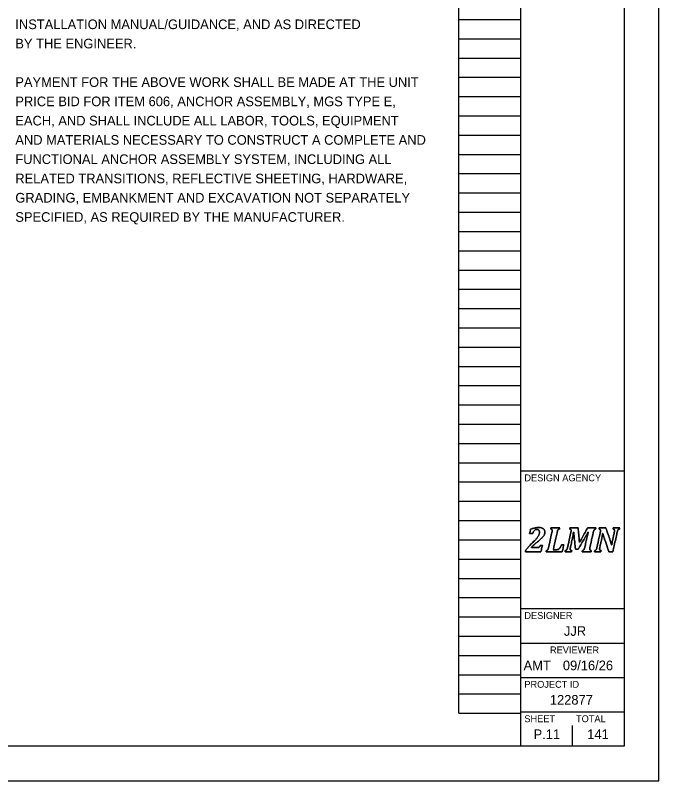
# Model space of a CAD drawing. Extents: x -17.1 to 50.1, y -5.2 to 23.
# Drawn here: x 24.66 to 34, y 0 to 11.12 of the extents above; entities that cross this region are included whole.
import ezdxf

# ---------------------------------------------------------------- set-up
doc = ezdxf.new("R2010")
doc.units = 0
for name, color, linetype in [('SH_Border', 7, 'Continuous'), ('SH_Cut_Line', 7, 'Continuous'), ('SH_Data', 7, 'Continuous'), ('SH_Text', 7, 'Continuous')]:
    doc.layers.add(name, color=color, linetype=linetype)

msp = doc.modelspace()

# ---------------------------------------------------------------- linework, layer by layer
at = {"layer": 'SH_Border'}
for p, q in [((32, 0.5), (32, 21.5)), ((32, 4.5), (33.5, 4.5)), ((32, 2.5), (33.5, 2.5)), ((32, 2), (33.5, 2)), ((32, 1.5), (33.5, 1.5)), ((32, 1), (33.5, 1))]:
    msp.add_line(p, q, dxfattribs=at)
msp.add_lwpolyline([(1.5, 21.5), (33.5, 21.5), (33.5, 0.5), (1.5, 0.5)], close=True, dxfattribs=at)
at = {"layer": 'SH_Cut_Line'}
msp.add_lwpolyline([(0, 0), (34, 0), (34, 22), (0, 22)], close=True, dxfattribs=at)
at = {"layer": 'SH_Data'}
for p, q in [((31.1, 0.98), (31.1, 21.14)), ((32, 0.98), (32, 21.14)), ((31.1, 11.06), (32, 11.06)), ((31.1, 10.78), (32, 10.78)), ((31.1, 10.5), (32, 10.5)), ((31.1, 10.22), (32, 10.22)), ((31.1, 9.94), (32, 9.94)), ((31.1, 9.66), (32, 9.66)), ((31.1, 9.38), (32, 9.38)), ((31.1, 9.1), (32, 9.1)), ((31.1, 8.82), (32, 8.82)), ((31.1, 8.54), (32, 8.54)), ((31.1, 8.26), (32, 8.26)), ((31.1, 7.98), (32, 7.98)), ((31.1, 7.7), (32, 7.7)), ((31.1, 7.42), (32, 7.42)), ((31.1, 7.14), (32, 7.14)), ((31.1, 6.86), (32, 6.86)), ((31.1, 6.58), (32, 6.58)), ((31.1, 6.3), (32, 6.3)), ((31.1, 6.02), (32, 6.02)), ((31.1, 5.74), (32, 5.74)), ((31.1, 5.46), (32, 5.46)), ((31.1, 5.18), (32, 5.18)), ((31.1, 4.9), (32, 4.9)), ((31.1, 4.62), (32, 4.62)), ((31.1, 4.34), (32, 4.34)), ((31.1, 4.06), (32, 4.06)), ((31.1, 3.78), (32, 3.78)), ((31.1, 3.5), (32, 3.5)), ((32.75, 3.5), (32.75, 3.5)), ((31.1, 3.22), (32, 3.22)), ((31.1, 2.94), (32, 2.94)), ((31.1, 2.66), (32, 2.66)), ((31.1, 2.38), (32, 2.38)), ((31.1, 2.1), (32, 2.1)), ((31.1, 1.82), (32, 1.82)), ((31.1, 1.54), (32, 1.54)), ((31.1, 1.26), (32, 1.26)), ((31.1, 0.98), (32, 0.98)), ((32.75, 0.5), (32.75, 0.8)), ((32.375, 0.675), (32.375, 0.675))]:
    msp.add_line(p, q, dxfattribs=at)
for points in [[(32.237, 3.388), (32.246, 3.388), (32.253, 3.389), (32.258, 3.39), (32.263, 3.392), (32.267, 3.394), (32.27, 3.397), (32.273, 3.401), (32.277, 3.408), (32.281, 3.417), (32.281, 3.417), (32.312, 3.417), (32.312, 3.417), (32.312, 3.417), (32.29, 3.326), (32.29, 3.326), (32.29, 3.326), (32.066, 3.326), (32.066, 3.326), (32.066, 3.326), (32.069, 3.343), (32.069, 3.343), (32.078, 3.358), (32.091, 3.375), (32.106, 3.394), (32.122, 3.412), (32.144, 3.435), (32.172, 3.462), (32.197, 3.486), (32.217, 3.506), (32.23, 3.521), (32.243, 3.537), (32.253, 3.551), (32.259, 3.566), (32.266, 3.58), (32.269, 3.595), (32.269, 3.61), (32.269, 3.622), (32.266, 3.632), (32.26, 3.64), (32.253, 3.647), (32.245, 3.65), (32.234, 3.65), (32.22, 3.65), (32.208, 3.646), (32.198, 3.636), (32.188, 3.627), (32.18, 3.613), (32.172, 3.593), (32.172, 3.593), (32.126, 3.593), (32.126, 3.593), (32.126, 3.593), (32.14, 3.654), (32.14, 3.654), (32.166, 3.663), (32.188, 3.669), (32.205, 3.673), (32.223, 3.676), (32.24, 3.678), (32.258, 3.678), (32.278, 3.678), (32.295, 3.675), (32.309, 3.669), (32.322, 3.664), (32.332, 3.656), (32.339, 3.646), (32.345, 3.637), (32.348, 3.626), (32.348, 3.613), (32.348, 3.602), (32.346, 3.591), (32.342, 3.581), (32.339, 3.571), (32.333, 3.56), (32.324, 3.549), (32.315, 3.539), (32.304, 3.526), (32.289, 3.513), (32.275, 3.499), (32.254, 3.482), (32.228, 3.46), (32.216, 3.45), (32.202, 3.438), (32.188, 3.425), (32.174, 3.412), (32.162, 3.4), (32.154, 3.391), (32.154, 3.391), (32.153, 3.388), (32.153, 3.388), (32.153, 3.388), (32.237, 3.388), (32.237, 3.388)], [(32.237, 3.388), (32.237, 3.388), (32.153, 3.388), (32.153, 3.388), (32.153, 3.388), (32.154, 3.391), (32.154, 3.391), (32.162, 3.4), (32.174, 3.412), (32.188, 3.425), (32.202, 3.438), (32.216, 3.45), (32.228, 3.46), (32.254, 3.482), (32.275, 3.499), (32.289, 3.513), (32.304, 3.526), (32.315, 3.539), (32.324, 3.549), (32.333, 3.56), (32.339, 3.571), (32.342, 3.581), (32.346, 3.591), (32.348, 3.602), (32.348, 3.613), (32.348, 3.626), (32.345, 3.637), (32.339, 3.646), (32.332, 3.656), (32.322, 3.664), (32.309, 3.669), (32.295, 3.675), (32.278, 3.678), (32.258, 3.678), (32.24, 3.678), (32.223, 3.676), (32.205, 3.673), (32.188, 3.669), (32.166, 3.663), (32.14, 3.654), (32.14, 3.654), (32.126, 3.593), (32.126, 3.593), (32.126, 3.593), (32.172, 3.593), (32.172, 3.593), (32.18, 3.613), (32.188, 3.627), (32.198, 3.636), (32.208, 3.646), (32.22, 3.65), (32.234, 3.65), (32.245, 3.65), (32.253, 3.647), (32.26, 3.64), (32.266, 3.632), (32.269, 3.622), (32.269, 3.61), (32.269, 3.595), (32.266, 3.58), (32.259, 3.566), (32.253, 3.551), (32.243, 3.537), (32.23, 3.521), (32.217, 3.506), (32.197, 3.486), (32.172, 3.462), (32.144, 3.435), (32.122, 3.412), (32.106, 3.394), (32.091, 3.375), (32.078, 3.358), (32.069, 3.343), (32.069, 3.343), (32.066, 3.326), (32.066, 3.326), (32.066, 3.326), (32.29, 3.326), (32.29, 3.326), (32.29, 3.326), (32.312, 3.417), (32.312, 3.417), (32.312, 3.417), (32.281, 3.417), (32.281, 3.417), (32.277, 3.408), (32.273, 3.401), (32.27, 3.397), (32.267, 3.394), (32.263, 3.392), (32.258, 3.39), (32.253, 3.389), (32.246, 3.388), (32.237, 3.388)], [(32.518, 3.356), (32.527, 3.356), (32.533, 3.357), (32.538, 3.358), (32.542, 3.36), (32.546, 3.362), (32.55, 3.365), (32.554, 3.368), (32.558, 3.372), (32.562, 3.377), (32.567, 3.382), (32.571, 3.388), (32.576, 3.397), (32.58, 3.405), (32.585, 3.415), (32.589, 3.427), (32.589, 3.427), (32.624, 3.427), (32.624, 3.427), (32.624, 3.427), (32.598, 3.326), (32.598, 3.326), (32.598, 3.326), (32.365, 3.326), (32.365, 3.326), (32.365, 3.326), (32.369, 3.343), (32.369, 3.343), (32.376, 3.345), (32.381, 3.348), (32.385, 3.351), (32.389, 3.355), (32.392, 3.36), (32.395, 3.366), (32.398, 3.373), (32.4, 3.382), (32.403, 3.395), (32.403, 3.395), (32.449, 3.605), (32.449, 3.605), (32.452, 3.615), (32.453, 3.625), (32.453, 3.635), (32.453, 3.642), (32.451, 3.647), (32.448, 3.651), (32.444, 3.654), (32.439, 3.656), (32.432, 3.657), (32.432, 3.657), (32.435, 3.674), (32.435, 3.674), (32.435, 3.674), (32.563, 3.674), (32.563, 3.674), (32.563, 3.674), (32.559, 3.657), (32.559, 3.657), (32.552, 3.655), (32.547, 3.652), (32.543, 3.649), (32.539, 3.645), (32.536, 3.64), (32.533, 3.634), (32.531, 3.627), (32.528, 3.618), (32.525, 3.605), (32.525, 3.605), (32.47, 3.356), (32.47, 3.356), (32.47, 3.356), (32.518, 3.356), (32.518, 3.356)], [(32.518, 3.356), (32.518, 3.356), (32.47, 3.356), (32.47, 3.356), (32.47, 3.356), (32.525, 3.605), (32.525, 3.605), (32.528, 3.618), (32.531, 3.627), (32.533, 3.634), (32.536, 3.64), (32.539, 3.645), (32.543, 3.649), (32.547, 3.652), (32.552, 3.655), (32.559, 3.657), (32.559, 3.657), (32.563, 3.674), (32.563, 3.674), (32.563, 3.674), (32.435, 3.674), (32.435, 3.674), (32.435, 3.674), (32.432, 3.657), (32.432, 3.657), (32.439, 3.656), (32.444, 3.654), (32.448, 3.651), (32.451, 3.647), (32.453, 3.642), (32.453, 3.635), (32.453, 3.625), (32.452, 3.615), (32.449, 3.605), (32.449, 3.605), (32.403, 3.395), (32.403, 3.395), (32.4, 3.382), (32.398, 3.373), (32.395, 3.366), (32.392, 3.36), (32.389, 3.355), (32.385, 3.351), (32.381, 3.348), (32.376, 3.345), (32.369, 3.343), (32.369, 3.343), (32.365, 3.326), (32.365, 3.326), (32.365, 3.326), (32.598, 3.326), (32.598, 3.326), (32.598, 3.326), (32.624, 3.427), (32.624, 3.427), (32.624, 3.427), (32.589, 3.427), (32.589, 3.427), (32.585, 3.415), (32.58, 3.405), (32.576, 3.397), (32.571, 3.388), (32.567, 3.382), (32.562, 3.377), (32.558, 3.372), (32.554, 3.368), (32.55, 3.365), (32.546, 3.362), (32.542, 3.36), (32.538, 3.358), (32.533, 3.357), (32.527, 3.356), (32.518, 3.356)], [(32.829, 3.674), (32.829, 3.674), (32.849, 3.461), (32.849, 3.461), (32.849, 3.461), (32.969, 3.674), (32.969, 3.674), (32.969, 3.674), (33.087, 3.674), (33.087, 3.674), (33.087, 3.674), (33.084, 3.657), (33.084, 3.657), (33.077, 3.655), (33.071, 3.652), (33.067, 3.649), (33.064, 3.645), (33.06, 3.64), (33.058, 3.634), (33.055, 3.627), (33.052, 3.618), (33.05, 3.605), (33.05, 3.605), (33.003, 3.395), (33.003, 3.395), (33.002, 3.39), (33.002, 3.387), (33.001, 3.384), (33.001, 3.382), (33.001, 3.379), (33, 3.376), (33, 3.373), (33, 3.369), (33, 3.365), (33, 3.358), (33.002, 3.353), (33.005, 3.349), (33.008, 3.346), (33.014, 3.344), (33.021, 3.343), (33.021, 3.343), (33.018, 3.326), (33.018, 3.326), (33.018, 3.326), (32.89, 3.326), (32.89, 3.326), (32.89, 3.326), (32.893, 3.343), (32.893, 3.343), (32.9, 3.345), (32.906, 3.348), (32.91, 3.351), (32.914, 3.355), (32.917, 3.36), (32.919, 3.366), (32.922, 3.373), (32.925, 3.382), (32.928, 3.395), (32.928, 3.395), (32.951, 3.502), (32.951, 3.502), (32.954, 3.513), (32.957, 3.529), (32.962, 3.548), (32.967, 3.568), (32.972, 3.588), (32.978, 3.609), (32.978, 3.609), (32.973, 3.609), (32.973, 3.609), (32.965, 3.594), (32.957, 3.579), (32.948, 3.563), (32.948, 3.563), (32.833, 3.364), (32.833, 3.364), (32.833, 3.364), (32.792, 3.364), (32.792, 3.364), (32.792, 3.364), (32.775, 3.518), (32.775, 3.518), (32.773, 3.537), (32.772, 3.554), (32.77, 3.569), (32.769, 3.583), (32.768, 3.597), (32.768, 3.611), (32.768, 3.611), (32.764, 3.611), (32.764, 3.611), (32.761, 3.596), (32.758, 3.578), (32.755, 3.558), (32.751, 3.538), (32.747, 3.521), (32.744, 3.507), (32.744, 3.507), (32.72, 3.395), (32.72, 3.395), (32.719, 3.39), (32.718, 3.387), (32.718, 3.384), (32.717, 3.382), (32.717, 3.379), (32.717, 3.376), (32.717, 3.373), (32.716, 3.369), (32.716, 3.365), (32.716, 3.358), (32.718, 3.353), (32.721, 3.349), (32.725, 3.346), (32.73, 3.344), (32.738, 3.343), (32.738, 3.343), (32.734, 3.326), (32.734, 3.326), (32.734, 3.326), (32.641, 3.326), (32.641, 3.326), (32.641, 3.326), (32.644, 3.343), (32.644, 3.343), (32.651, 3.345), (32.657, 3.348), (32.661, 3.351), (32.665, 3.355), (32.668, 3.36), (32.67, 3.366), (32.673, 3.373), (32.676, 3.382), (32.679, 3.395), (32.679, 3.395), (32.725, 3.605), (32.725, 3.605), (32.727, 3.615), (32.728, 3.625), (32.728, 3.635), (32.728, 3.642), (32.727, 3.647), (32.723, 3.651), (32.72, 3.654), (32.715, 3.656), (32.707, 3.657), (32.707, 3.657), (32.711, 3.674), (32.711, 3.674), (32.711, 3.674), (32.829, 3.674), (32.829, 3.674)], [(32.829, 3.674), (32.829, 3.674), (32.711, 3.674), (32.711, 3.674), (32.711, 3.674), (32.707, 3.657), (32.707, 3.657), (32.715, 3.656), (32.72, 3.654), (32.723, 3.651), (32.727, 3.647), (32.728, 3.642), (32.728, 3.635), (32.728, 3.625), (32.727, 3.615), (32.725, 3.605), (32.725, 3.605), (32.679, 3.395), (32.679, 3.395), (32.676, 3.382), (32.673, 3.373), (32.67, 3.366), (32.668, 3.36), (32.665, 3.355), (32.661, 3.351), (32.657, 3.348), (32.651, 3.345), (32.644, 3.343), (32.644, 3.343), (32.641, 3.326), (32.641, 3.326), (32.641, 3.326), (32.734, 3.326), (32.734, 3.326), (32.734, 3.326), (32.738, 3.343), (32.738, 3.343), (32.73, 3.344), (32.725, 3.346), (32.721, 3.349), (32.718, 3.353), (32.716, 3.358), (32.716, 3.365), (32.716, 3.369), (32.717, 3.373), (32.717, 3.376), (32.717, 3.379), (32.717, 3.382), (32.718, 3.384), (32.718, 3.387), (32.719, 3.39), (32.72, 3.395), (32.72, 3.395), (32.744, 3.507), (32.744, 3.507), (32.747, 3.521), (32.751, 3.538), (32.755, 3.558), (32.758, 3.578), (32.761, 3.596), (32.764, 3.611), (32.764, 3.611), (32.768, 3.611), (32.768, 3.611), (32.768, 3.597), (32.769, 3.583), (32.77, 3.569), (32.772, 3.554), (32.773, 3.537), (32.775, 3.518), (32.775, 3.518), (32.792, 3.364), (32.792, 3.364), (32.792, 3.364), (32.833, 3.364), (32.833, 3.364), (32.833, 3.364), (32.948, 3.563), (32.948, 3.563), (32.957, 3.579), (32.965, 3.594), (32.973, 3.609), (32.973, 3.609), (32.978, 3.609), (32.978, 3.609), (32.972, 3.588), (32.967, 3.568), (32.962, 3.548), (32.957, 3.529), (32.954, 3.513), (32.951, 3.502), (32.951, 3.502), (32.928, 3.395), (32.928, 3.395), (32.925, 3.382), (32.922, 3.373), (32.919, 3.366), (32.917, 3.36), (32.914, 3.355), (32.91, 3.351), (32.906, 3.348), (32.9, 3.345), (32.893, 3.343), (32.893, 3.343), (32.89, 3.326), (32.89, 3.326), (32.89, 3.326), (33.018, 3.326), (33.018, 3.326), (33.018, 3.326), (33.021, 3.343), (33.021, 3.343), (33.014, 3.344), (33.008, 3.346), (33.005, 3.349), (33.002, 3.353), (33, 3.358), (33, 3.365), (33, 3.369), (33, 3.373), (33, 3.376), (33.001, 3.379), (33.001, 3.382), (33.001, 3.384), (33.002, 3.387), (33.002, 3.39), (33.003, 3.395), (33.003, 3.395), (33.05, 3.605), (33.05, 3.605), (33.052, 3.618), (33.055, 3.627), (33.058, 3.634), (33.06, 3.64), (33.064, 3.645), (33.067, 3.649), (33.071, 3.652), (33.077, 3.655), (33.084, 3.657), (33.084, 3.657), (33.087, 3.674), (33.087, 3.674), (33.087, 3.674), (32.969, 3.674), (32.969, 3.674), (32.969, 3.674), (32.849, 3.461), (32.849, 3.461), (32.849, 3.461), (32.829, 3.674), (32.829, 3.674)], [(33.137, 3.674), (33.137, 3.674), (33.234, 3.674), (33.234, 3.674), (33.234, 3.674), (33.283, 3.53), (33.283, 3.53), (33.296, 3.49), (33.307, 3.456), (33.315, 3.426), (33.315, 3.426), (33.318, 3.426), (33.318, 3.426), (33.323, 3.455), (33.329, 3.488), (33.337, 3.523), (33.337, 3.523), (33.355, 3.605), (33.355, 3.605), (33.357, 3.615), (33.358, 3.625), (33.358, 3.635), (33.358, 3.642), (33.357, 3.647), (33.353, 3.651), (33.35, 3.654), (33.345, 3.656), (33.337, 3.657), (33.337, 3.657), (33.341, 3.674), (33.341, 3.674), (33.341, 3.674), (33.434, 3.674), (33.434, 3.674), (33.434, 3.674), (33.431, 3.657), (33.431, 3.657), (33.424, 3.655), (33.418, 3.652), (33.414, 3.649), (33.41, 3.645), (33.407, 3.64), (33.405, 3.634), (33.402, 3.627), (33.399, 3.618), (33.396, 3.605), (33.396, 3.605), (33.335, 3.326), (33.335, 3.326), (33.335, 3.326), (33.277, 3.326), (33.277, 3.326), (33.277, 3.326), (33.216, 3.504), (33.216, 3.504), (33.211, 3.518), (33.207, 3.531), (33.204, 3.543), (33.2, 3.556), (33.195, 3.571), (33.19, 3.59), (33.19, 3.59), (33.186, 3.59), (33.186, 3.59), (33.185, 3.579), (33.182, 3.563), (33.179, 3.543), (33.175, 3.523), (33.17, 3.501), (33.165, 3.478), (33.165, 3.478), (33.147, 3.395), (33.147, 3.395), (33.146, 3.39), (33.145, 3.387), (33.145, 3.384), (33.144, 3.382), (33.144, 3.379), (33.144, 3.376), (33.143, 3.373), (33.143, 3.369), (33.143, 3.365), (33.143, 3.358), (33.145, 3.353), (33.148, 3.349), (33.152, 3.346), (33.157, 3.344), (33.164, 3.343), (33.164, 3.343), (33.161, 3.326), (33.161, 3.326), (33.161, 3.326), (33.067, 3.326), (33.067, 3.326), (33.067, 3.326), (33.071, 3.343), (33.071, 3.343), (33.078, 3.345), (33.083, 3.348), (33.087, 3.351), (33.091, 3.355), (33.094, 3.36), (33.097, 3.366), (33.1, 3.373), (33.102, 3.382), (33.105, 3.395), (33.105, 3.395), (33.151, 3.605), (33.151, 3.605), (33.154, 3.615), (33.155, 3.625), (33.155, 3.635), (33.155, 3.642), (33.153, 3.647), (33.15, 3.651), (33.146, 3.654), (33.141, 3.656), (33.134, 3.657), (33.134, 3.657), (33.137, 3.674), (33.137, 3.674)], [(33.137, 3.674), (33.137, 3.674), (33.134, 3.657), (33.134, 3.657), (33.141, 3.656), (33.146, 3.654), (33.15, 3.651), (33.153, 3.647), (33.155, 3.642), (33.155, 3.635), (33.155, 3.625), (33.154, 3.615), (33.151, 3.605), (33.151, 3.605), (33.105, 3.395), (33.105, 3.395), (33.102, 3.382), (33.1, 3.373), (33.097, 3.366), (33.094, 3.36), (33.091, 3.355), (33.087, 3.351), (33.083, 3.348), (33.078, 3.345), (33.071, 3.343), (33.071, 3.343), (33.067, 3.326), (33.067, 3.326), (33.067, 3.326), (33.161, 3.326), (33.161, 3.326), (33.161, 3.326), (33.164, 3.343), (33.164, 3.343), (33.157, 3.344), (33.152, 3.346), (33.148, 3.349), (33.145, 3.353), (33.143, 3.358), (33.143, 3.365), (33.143, 3.369), (33.143, 3.373), (33.144, 3.376), (33.144, 3.379), (33.144, 3.382), (33.145, 3.384), (33.145, 3.387), (33.146, 3.39), (33.147, 3.395), (33.147, 3.395), (33.165, 3.478), (33.165, 3.478), (33.17, 3.501), (33.175, 3.523), (33.179, 3.543), (33.182, 3.563), (33.185, 3.579), (33.186, 3.59), (33.186, 3.59), (33.19, 3.59), (33.19, 3.59), (33.195, 3.571), (33.2, 3.556), (33.204, 3.543), (33.207, 3.531), (33.211, 3.518), (33.216, 3.504), (33.216, 3.504), (33.277, 3.326), (33.277, 3.326), (33.277, 3.326), (33.335, 3.326), (33.335, 3.326), (33.335, 3.326), (33.396, 3.605), (33.396, 3.605), (33.399, 3.618), (33.402, 3.627), (33.405, 3.634), (33.407, 3.64), (33.41, 3.645), (33.414, 3.649), (33.418, 3.652), (33.424, 3.655), (33.431, 3.657), (33.431, 3.657), (33.434, 3.674), (33.434, 3.674), (33.434, 3.674), (33.341, 3.674), (33.341, 3.674), (33.341, 3.674), (33.337, 3.657), (33.337, 3.657), (33.345, 3.656), (33.35, 3.654), (33.353, 3.651), (33.357, 3.647), (33.358, 3.642), (33.358, 3.635), (33.358, 3.625), (33.357, 3.615), (33.355, 3.605), (33.355, 3.605), (33.337, 3.523), (33.337, 3.523), (33.329, 3.488), (33.323, 3.455), (33.318, 3.426), (33.318, 3.426), (33.315, 3.426), (33.315, 3.426), (33.307, 3.456), (33.296, 3.49), (33.283, 3.53), (33.283, 3.53), (33.234, 3.674), (33.234, 3.674), (33.234, 3.674), (33.137, 3.674), (33.137, 3.674)]]:
    msp.add_open_spline(points, degree=3, dxfattribs=at)

# ---------------------------------------------------------------- texts
for s, height, p in [('DESIGN AGENCY', 0.1, (32.05, 4.35)), ('DESIGNER', 0.1, (32.05, 2.35)), ('JJR', 0.14, (32.624, 2.105)), ('REVIEWER', 0.1, (32.422, 1.85)), ('AMT', 0.14, (32.039, 1.605)), ('09/16/26', 0.14, (32.609, 1.605)), ('PROJECT ID', 0.1, (32.05, 1.35)), ('122877', 0.14, (32.42, 1.105)), ('SHEET', 0.1, (32.05, 0.85)), ('TOTAL', 0.1, (32.8, 0.85)), ('P.11', 0.14, (32.184, 0.605)), ('141', 0.14, (32.963, 0.605))]:
    msp.add_text(s, height=height, dxfattribs=at).set_placement(p)
at = {"layer": 'SH_Text'}
for s, p in [('INSTALLATION MANUAL/GUIDANCE, AND AS DIRECTED', (24.66, 10.92)), ('BY THE ENGINEER.', (24.66, 10.64)), ('PAYMENT FOR THE ABOVE WORK SHALL BE MADE AT THE UNIT', (24.66, 10.08)), ('PRICE BID FOR ITEM 606, ANCHOR ASSEMBLY, MGS TYPE E,', (24.66, 9.8)), ('EACH, AND SHALL INCLUDE ALL LABOR, TOOLS, EQUIPMENT', (24.66, 9.52)), ('AND MATERIALS NECESSARY TO CONSTRUCT A COMPLETE AND', (24.66, 9.24)), ('FUNCTIONAL ANCHOR ASSEMBLY SYSTEM, INCLUDING ALL', (24.66, 8.96)), ('RELATED TRANSITIONS, REFLECTIVE SHEETING, HARDWARE,', (24.66, 8.68)), ('GRADING, EMBANKMENT AND EXCAVATION NOT SEPARATELY', (24.66, 8.4)), ('SPECIFIED, AS REQUIRED BY THE MANUFACTURER.', (24.66, 8.12))]:
    msp.add_text(s, height=0.14, dxfattribs=at).set_placement(p)

doc.saveas('drawing.dxf')
